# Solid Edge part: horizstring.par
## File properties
Author: harmonj5
Template: ansi part.par
Last saved by: harmonj5
Revision: 6
Application: Solid Edge
Accuracy: 0.990
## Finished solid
Body 1: solid body, 6 faces, 12 edges, 8 vertices.
  Faces by surface: plane 5, swept 1
  Edges by curve: line 10, spline 2
Bounding box of the edges (mm; curved faces can reach further): 5.461 x 527.050 x 3.302, from (-10.2133, 0, 9.1053) to (-4.7523, 527.05, 12.4073).
Planar faces by outward normal: +x 1, +y 1, +z 1, -y 1, -z 1
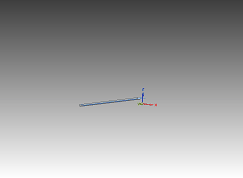
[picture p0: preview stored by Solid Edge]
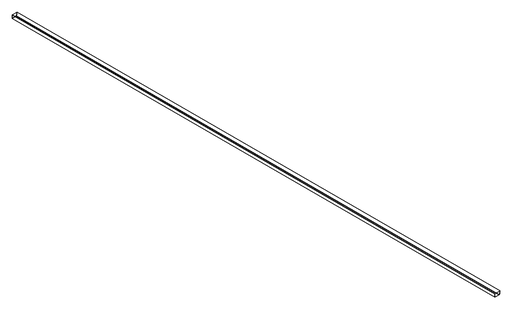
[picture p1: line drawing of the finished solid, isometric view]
